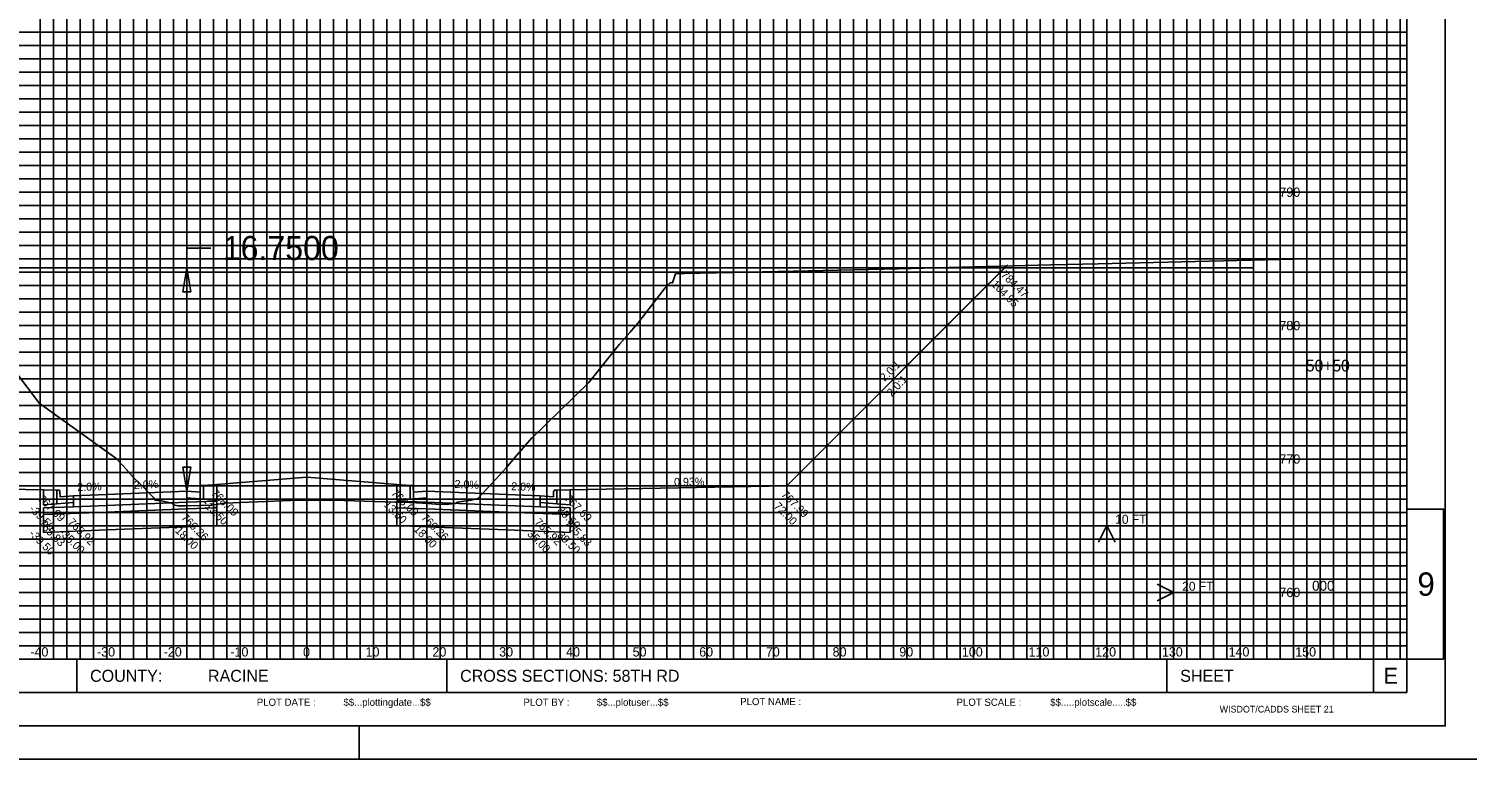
# Model space of a CAD drawing. Extents: x 578243 to 601557, y 174899 to 175559.
# Drawn here: x 600998.1 to 601213.9, y 175338.8 to 175448.3 of the extents above; entities that cross this region are included whole.
import ezdxf

# ---------------------------------------------------------------- set-up
doc = ezdxf.new("R2010")
doc.units = 0
for name, color, linetype in [('E_PROF_Grid', 7, 'Continuous'), ('E_PROF_GridMin', 7, 'Continuous'), ('P_CRDR_Label', 7, 'Continuous'), ('P_CRDR_Link', 7, 'Continuous'), ('P_E_XS_Ground', 7, 'Continuous'), ('P_RW_SlopeIntercepts', 7, 'Continuous'), ('P_XS_Text', 7, 'Continuous'), ('PLT_Sheet_Border', 7, 'Continuous'), ('PLT_Sheet_Info', 7, 'Continuous')]:
    doc.layers.add(name, color=color, linetype=linetype)

msp = doc.modelspace()

# ---------------------------------------------------------------- linework, layer by layer
at = {"layer": 'E_PROF_Grid'}
for p, q in [((600999.84, 175353.8), (600999.84, 175548.8)), ((601009.84, 175353.8), (601009.84, 175548.8)), ((601019.84, 175353.8), (601019.84, 175548.8)), ((601029.84, 175353.8), (601029.84, 175548.8)), ((601039.84, 175353.8), (601039.84, 175548.8)), ((601049.84, 175353.8), (601049.84, 175548.8)), ((601059.84, 175353.8), (601059.84, 175548.8)), ((601069.84, 175353.8), (601069.84, 175548.8)), ((601079.84, 175353.8), (601079.84, 175548.8)), ((601089.84, 175353.8), (601089.84, 175548.8)), ((601099.84, 175353.8), (601099.84, 175548.8)), ((601109.84, 175353.8), (601109.84, 175548.8)), ((601119.84, 175353.8), (601119.84, 175548.8)), ((601129.84, 175353.8), (601129.84, 175548.8)), ((601139.84, 175353.8), (601139.84, 175548.8)), ((601149.84, 175353.8), (601149.84, 175548.8)), ((601159.84, 175353.8), (601159.84, 175548.8)), ((601169.84, 175353.8), (601169.84, 175548.8)), ((601179.84, 175353.8), (601179.84, 175548.8)), ((601189.84, 175353.8), (601189.84, 175548.8)), ((601199.84, 175353.8), (601199.84, 175548.8)), ((600889.84, 175443.8), (601204.84, 175443.8)), ((600889.84, 175433.8), (601204.84, 175433.8)), ((600889.84, 175423.8), (601204.84, 175423.8)), ((600889.84, 175413.8), (601204.84, 175413.8)), ((600889.84, 175403.8), (601204.84, 175403.8)), ((600889.84, 175393.8), (601204.84, 175393.8)), ((600889.84, 175383.8), (601204.84, 175383.8)), ((600889.84, 175373.8), (601204.84, 175373.8)), ((600889.84, 175363.8), (601204.84, 175363.8))]:
    msp.add_line(p, q, dxfattribs=at)
at = {"layer": 'E_PROF_GridMin'}
for p, q in [((601001.84, 175353.8), (601001.84, 175548.8)), ((601003.84, 175353.8), (601003.84, 175548.8)), ((601005.84, 175353.8), (601005.84, 175548.8)), ((601007.84, 175353.8), (601007.84, 175548.8)), ((601011.84, 175353.8), (601011.84, 175548.8)), ((601013.84, 175353.8), (601013.84, 175548.8)), ((601015.84, 175353.8), (601015.84, 175548.8)), ((601017.84, 175353.8), (601017.84, 175548.8)), ((601021.84, 175353.8), (601021.84, 175548.8)), ((601023.84, 175353.8), (601023.84, 175548.8)), ((601025.84, 175353.8), (601025.84, 175548.8)), ((601027.84, 175353.8), (601027.84, 175548.8)), ((601031.84, 175353.8), (601031.84, 175548.8)), ((601033.84, 175353.8), (601033.84, 175548.8)), ((601035.84, 175353.8), (601035.84, 175548.8)), ((601037.84, 175353.8), (601037.84, 175548.8)), ((601041.84, 175353.8), (601041.84, 175548.8)), ((601043.84, 175353.8), (601043.84, 175548.8)), ((601045.84, 175353.8), (601045.84, 175548.8)), ((601047.84, 175353.8), (601047.84, 175548.8)), ((601051.84, 175353.8), (601051.84, 175548.8)), ((601053.84, 175353.8), (601053.84, 175548.8)), ((601055.84, 175353.8), (601055.84, 175548.8)), ((601057.84, 175353.8), (601057.84, 175548.8)), ((601061.84, 175353.8), (601061.84, 175548.8)), ((601063.84, 175353.8), (601063.84, 175548.8)), ((601065.84, 175353.8), (601065.84, 175548.8)), ((601067.84, 175353.8), (601067.84, 175548.8)), ((601071.84, 175353.8), (601071.84, 175548.8)), ((601073.84, 175353.8), (601073.84, 175548.8)), ((601075.84, 175353.8), (601075.84, 175548.8)), ((601077.84, 175353.8), (601077.84, 175548.8)), ((601081.84, 175353.8), (601081.84, 175548.8)), ((601083.84, 175353.8), (601083.84, 175548.8)), ((601085.84, 175353.8), (601085.84, 175548.8)), ((601087.84, 175353.8), (601087.84, 175548.8)), ((601091.84, 175353.8), (601091.84, 175548.8)), ((601093.84, 175353.8), (601093.84, 175548.8)), ((601095.84, 175353.8), (601095.84, 175548.8)), ((601097.84, 175353.8), (601097.84, 175548.8)), ((601101.84, 175353.8), (601101.84, 175548.8)), ((601103.84, 175353.8), (601103.84, 175548.8)), ((601105.84, 175353.8), (601105.84, 175548.8)), ((601107.84, 175353.8), (601107.84, 175548.8)), ((601111.84, 175353.8), (601111.84, 175548.8)), ((601113.84, 175353.8), (601113.84, 175548.8)), ((601115.84, 175353.8), (601115.84, 175548.8)), ((601117.84, 175353.8), (601117.84, 175548.8)), ((601121.84, 175353.8), (601121.84, 175548.8)), ((601123.84, 175353.8), (601123.84, 175548.8)), ((601125.84, 175353.8), (601125.84, 175548.8)), ((601127.84, 175353.8), (601127.84, 175548.8)), ((601131.84, 175353.8), (601131.84, 175548.8)), ((601133.84, 175353.8), (601133.84, 175548.8)), ((601135.84, 175353.8), (601135.84, 175548.8)), ((601137.84, 175353.8), (601137.84, 175548.8)), ((601141.84, 175353.8), (601141.84, 175548.8)), ((601143.84, 175353.8), (601143.84, 175548.8)), ((601145.84, 175353.8), (601145.84, 175548.8)), ((601147.84, 175353.8), (601147.84, 175548.8)), ((601151.84, 175353.8), (601151.84, 175548.8)), ((601153.84, 175353.8), (601153.84, 175548.8)), ((601155.84, 175353.8), (601155.84, 175548.8)), ((601157.84, 175353.8), (601157.84, 175548.8)), ((601161.84, 175353.8), (601161.84, 175548.8)), ((601163.84, 175353.8), (601163.84, 175548.8)), ((601165.84, 175353.8), (601165.84, 175548.8)), ((601167.84, 175353.8), (601167.84, 175548.8)), ((601171.84, 175353.8), (601171.84, 175548.8)), ((601173.84, 175353.8), (601173.84, 175548.8)), ((601175.84, 175353.8), (601175.84, 175548.8)), ((601177.84, 175353.8), (601177.84, 175548.8)), ((601181.84, 175353.8), (601181.84, 175548.8)), ((601183.84, 175353.8), (601183.84, 175548.8)), ((601185.84, 175353.8), (601185.84, 175548.8)), ((601187.84, 175353.8), (601187.84, 175548.8)), ((601191.84, 175353.8), (601191.84, 175548.8)), ((601193.84, 175353.8), (601193.84, 175548.8)), ((601195.84, 175353.8), (601195.84, 175548.8)), ((601197.84, 175353.8), (601197.84, 175548.8)), ((601201.84, 175353.8), (601201.84, 175548.8)), ((601203.84, 175353.8), (601203.84, 175548.8)), ((600889.84, 175447.8), (601204.84, 175447.8)), ((600889.84, 175445.8), (601204.84, 175445.8)), ((600889.84, 175441.8), (601204.84, 175441.8)), ((600889.84, 175439.8), (601204.84, 175439.8)), ((600889.84, 175437.8), (601204.84, 175437.8)), ((600889.84, 175435.8), (601204.84, 175435.8)), ((600889.84, 175431.8), (601204.84, 175431.8)), ((600889.84, 175429.8), (601204.84, 175429.8)), ((600889.84, 175427.8), (601204.84, 175427.8)), ((600889.84, 175425.8), (601204.84, 175425.8)), ((600889.84, 175421.8), (601204.84, 175421.8)), ((600889.84, 175419.8), (601204.84, 175419.8)), ((600889.84, 175417.8), (601204.84, 175417.8)), ((600889.84, 175415.8), (601204.84, 175415.8)), ((600889.84, 175411.8), (601204.84, 175411.8)), ((600889.84, 175409.8), (601204.84, 175409.8)), ((600889.84, 175407.8), (601204.84, 175407.8)), ((600889.84, 175405.8), (601204.84, 175405.8)), ((600889.84, 175401.8), (601204.84, 175401.8)), ((600889.84, 175399.8), (601204.84, 175399.8)), ((600889.84, 175397.8), (601204.84, 175397.8)), ((600889.84, 175395.8), (601204.84, 175395.8)), ((600889.84, 175391.8), (601204.84, 175391.8)), ((600889.84, 175389.8), (601204.84, 175389.8)), ((600889.84, 175387.8), (601204.84, 175387.8)), ((600889.84, 175385.8), (601204.84, 175385.8)), ((600889.84, 175381.8), (601204.84, 175381.8)), ((600889.84, 175379.8), (601204.84, 175379.8)), ((600889.84, 175377.8), (601204.84, 175377.8)), ((600889.84, 175375.8), (601204.84, 175375.8)), ((600889.84, 175371.8), (601204.84, 175371.8)), ((600889.84, 175369.8), (601204.84, 175369.8)), ((600889.84, 175367.8), (601204.84, 175367.8)), ((600889.84, 175365.8), (601204.84, 175365.8)), ((600889.84, 175361.8), (601204.84, 175361.8)), ((600889.84, 175359.8), (601204.84, 175359.8)), ((600889.84, 175357.8), (601204.84, 175357.8)), ((600889.84, 175355.8), (601204.84, 175355.8)), ((601207.19, 175338.8), (601217.19, 175338.8))]:
    msp.add_line(p, q, dxfattribs=at)
at = {"layer": 'P_CRDR_Link'}
msp.add_line((601144.95, 175412.9), (601111.84, 175379.78), dxfattribs=at)
for points in [[(601111.84, 175379.78), (601144.78, 175412.73)], [(601111.84, 175379.78), (601144.78, 175412.73)], [(601026.34, 175379.98), (601039.84, 175381.06)], [(601026.34, 175379.98), (601039.84, 175381.06)], [(601039.84, 175381.06), (601026.34, 175379.98)], [(601039.84, 175381.06), (601053.34, 175379.98)], [(601039.84, 175381.06), (601053.34, 175379.98)], [(601053.34, 175379.98), (601039.84, 175381.06)], [(601000.34, 175379.18), (600967.84, 175379.78)], [(601000.34, 175379.18), (600967.84, 175379.78)], [(601002.34, 175379.14), (601000.34, 175379.18)], [(601000.34, 175379.18), (601000.34, 175376.94)], [(601000.34, 175379.18), (601000.34, 175376.94)], [(601000.34, 175379.18), (601000.34, 175376.94)], [(601002.66, 175379.14), (601002.34, 175379.14)], [(601002.66, 175379.14), (601002.34, 175379.14)], [(601002.34, 175379.14), (601002.34, 175377.1)], [(601002.34, 175377.1), (601002.34, 175379.14)], [(601002.74, 175379.1), (601002.66, 175379.14)], [(601002.74, 175379.1), (601002.66, 175379.14)], [(601002.8, 175378.98), (601002.74, 175379.1)], [(601002.8, 175378.98), (601002.74, 175379.1)], [(601002.82, 175378.82), (601002.8, 175378.98)], [(601002.82, 175378.82), (601002.8, 175378.98)], [(601002.84, 175378.14), (601002.82, 175378.82)], [(601002.84, 175378.14), (601002.82, 175378.82)], [(601004.84, 175378.3), (601002.84, 175378.14)], [(601004.84, 175378.3), (601002.84, 175378.14)], [(601009.84, 175378.5), (601004.84, 175378.3)], [(601004.84, 175378.3), (601004.84, 175376.64)], [(601004.84, 175377.3), (601004.84, 175378.3)], [(601021.84, 175378.98), (601009.84, 175378.5)], [(601009.84, 175378.5), (601009.84, 175376.84)], [(601009.84, 175378.5), (601009.84, 175376.84)], [(601021.84, 175378.98), (601021.84, 175377.32)], [(601021.84, 175378.98), (601021.84, 175377.32)], [(601021.84, 175378.98), (601021.84, 175377.32)], [(601021.84, 175378.98), (601023.84, 175378.82)], [(601021.84, 175378.98), (601023.84, 175378.82)], [(601021.84, 175377.98), (601021.84, 175378.98)], [(601023.84, 175378.82), (601023.85, 175379.5)], [(601023.84, 175378.82), (601023.85, 175379.5)], [(601023.85, 175379.5), (601023.88, 175379.66)], [(601023.85, 175379.5), (601023.88, 175379.66)], [(601023.88, 175379.66), (601023.94, 175379.78)], [(601023.88, 175379.66), (601023.94, 175379.78)], [(601023.94, 175379.78), (601024.02, 175379.82)], [(601023.94, 175379.78), (601024.02, 175379.82)], [(601024.02, 175379.82), (601024.34, 175379.82)], [(601024.02, 175379.82), (601024.34, 175379.82)], [(601024.34, 175379.82), (601026.34, 175379.98)], [(601024.34, 175379.82), (601024.34, 175377.78)], [(601024.34, 175377.78), (601024.34, 175379.82)], [(601026.34, 175379.98), (601026.34, 175377.62)], [(601026.34, 175379.98), (601026.34, 175377.62)], [(601026.34, 175379.98), (601026.34, 175377.62)], [(601026.34, 175379.98), (601026.34, 175379.98)], [(601026.34, 175379.98), (601026.34, 175379.98)], [(601026.34, 175379.98), (601026.34, 175379.98)], [(601055.34, 175379.82), (601053.34, 175379.98)], [(601053.34, 175379.98), (601053.34, 175377.62)], [(601053.34, 175379.98), (601053.34, 175377.62)], [(601053.34, 175379.98), (601053.34, 175377.62)], [(601053.34, 175379.98), (601053.34, 175379.98)], [(601053.34, 175379.98), (601053.34, 175379.98)], [(601053.34, 175379.98), (601053.34, 175379.98)], [(601055.66, 175379.82), (601055.34, 175379.82)], [(601055.66, 175379.82), (601055.34, 175379.82)], [(601055.34, 175379.82), (601055.34, 175377.78)], [(601055.34, 175377.78), (601055.34, 175379.82)], [(601055.74, 175379.78), (601055.66, 175379.82)], [(601055.74, 175379.78), (601055.66, 175379.82)], [(601055.8, 175379.66), (601055.74, 175379.78)], [(601055.8, 175379.66), (601055.74, 175379.78)], [(601055.82, 175379.5), (601055.8, 175379.66)], [(601055.82, 175379.5), (601055.8, 175379.66)], [(601055.84, 175378.82), (601055.82, 175379.5)], [(601055.84, 175378.82), (601055.82, 175379.5)], [(601057.84, 175378.98), (601055.84, 175378.82)], [(601057.84, 175378.98), (601055.84, 175378.82)], [(601057.84, 175378.98), (601069.84, 175378.5)], [(601057.84, 175378.98), (601057.84, 175377.32)], [(601057.84, 175378.98), (601057.84, 175377.32)], [(601057.84, 175378.98), (601057.84, 175377.32)], [(601057.84, 175377.98), (601057.84, 175378.98)], [(601069.84, 175378.5), (601069.84, 175376.84)], [(601069.84, 175378.5), (601074.84, 175378.3)], [(601069.84, 175378.5), (601069.84, 175376.84)], [(601074.84, 175378.3), (601074.84, 175376.64)], [(601074.84, 175378.3), (601076.84, 175378.14)], [(601074.84, 175378.3), (601076.84, 175378.14)], [(601074.84, 175377.3), (601074.84, 175378.3)], [(601076.84, 175378.14), (601076.85, 175378.82)], [(601076.84, 175378.14), (601076.85, 175378.82)], [(601076.85, 175378.82), (601076.88, 175378.98)], [(601076.85, 175378.82), (601076.88, 175378.98)], [(601076.88, 175378.98), (601076.94, 175379.1)], [(601076.88, 175378.98), (601076.94, 175379.1)], [(601076.94, 175379.1), (601077.02, 175379.14)], [(601076.94, 175379.1), (601077.02, 175379.14)], [(601077.02, 175379.14), (601077.34, 175379.14)], [(601077.02, 175379.14), (601077.34, 175379.14)], [(601077.34, 175379.14), (601079.34, 175379.18)], [(601077.34, 175379.14), (601077.34, 175377.1)], [(601077.34, 175377.1), (601077.34, 175379.14)], [(601079.34, 175379.18), (601111.84, 175379.78)], [(601079.34, 175379.18), (601111.84, 175379.78)], [(601079.34, 175379.18), (601079.34, 175376.94)], [(601079.34, 175379.18), (601079.34, 175376.94)], [(601079.34, 175379.18), (601079.34, 175376.94)], [(601000.34, 175376.94), (601002.34, 175377.1)], [(601004.84, 175376.64), (601000.34, 175376.46)], [(601000.34, 175376.46), (601000.34, 175375.46)], [(601002.34, 175377.1), (601004.84, 175377.3)], [(601002.34, 175377.1), (601004.84, 175377.3)], [(601009.84, 175376.84), (601004.84, 175376.64)], [(601021.84, 175377.32), (601009.84, 175376.84)], [(601009.84, 175376.84), (601009.84, 175375.84)], [(601009.84, 175376.84), (601009.84, 175375.84)], [(601021.84, 175376.32), (601009.84, 175375.84)], [(601024.34, 175377.78), (601021.84, 175377.98)], [(601024.34, 175377.78), (601021.84, 175377.98)], [(601026.34, 175377.5), (601021.84, 175377.32)], [(601021.84, 175377.32), (601021.84, 175376.32)], [(601021.84, 175377.32), (601021.84, 175376.32)], [(601021.84, 175377.32), (601021.84, 175376.32)], [(601026.34, 175376.5), (601021.84, 175376.32)], [(601021.84, 175376.32), (601021.84, 175373.65)], [(601021.84, 175376.32), (601021.84, 175373.65)], [(601021.84, 175376.32), (601021.84, 175373.65)], [(601026.34, 175377.62), (601024.34, 175377.78)], [(601026.34, 175377.5), (601026.34, 175376.5)], [(601026.34, 175376.5), (601026.34, 175373.83)], [(601053.34, 175377.62), (601055.34, 175377.78)], [(601053.34, 175377.5), (601057.84, 175377.32)], [(601053.34, 175377.5), (601053.34, 175376.5)], [(601053.34, 175376.5), (601057.84, 175376.32)], [(601053.34, 175376.5), (601053.34, 175373.83)], [(601055.34, 175377.78), (601057.84, 175377.98)], [(601055.34, 175377.78), (601057.84, 175377.98)], [(601057.84, 175377.32), (601069.84, 175376.84)], [(601057.84, 175377.32), (601057.84, 175376.32)], [(601057.84, 175377.32), (601057.84, 175376.32)], [(601057.84, 175377.32), (601057.84, 175376.32)], [(601057.84, 175376.32), (601069.84, 175375.84)], [(601057.84, 175376.32), (601057.84, 175373.65)], [(601057.84, 175376.32), (601057.84, 175373.65)], [(601057.84, 175376.32), (601057.84, 175373.65)], [(601069.84, 175376.84), (601069.84, 175375.84)], [(601069.84, 175376.84), (601074.84, 175376.64)], [(601069.84, 175376.84), (601069.84, 175375.84)], [(601077.34, 175377.1), (601074.84, 175377.3)], [(601077.34, 175377.1), (601074.84, 175377.3)], [(601074.84, 175376.64), (601079.34, 175376.46)], [(601079.34, 175376.94), (601077.34, 175377.1)], [(601079.34, 175376.46), (601079.34, 175375.46)], [(601009.84, 175375.84), (601000.34, 175375.46)], [(601000.34, 175375.46), (601000.34, 175372.79)], [(601009.84, 175375.84), (601009.84, 175373.17)], [(601009.84, 175375.84), (601009.84, 175373.17)], [(601021.84, 175373.65), (601026.34, 175373.83)], [(601057.84, 175373.65), (601053.34, 175373.83)], [(601069.84, 175375.84), (601069.84, 175373.17)], [(601069.84, 175375.84), (601079.34, 175375.46)], [(601069.84, 175375.84), (601069.84, 175373.17)], [(601079.34, 175375.46), (601079.34, 175372.79)], [(601009.84, 175373.17), (601000.34, 175372.79)], [(601021.84, 175373.65), (601009.84, 175373.17)], [(601057.84, 175373.65), (601069.84, 175373.17)], [(601069.84, 175373.17), (601079.34, 175372.79)]]:
    msp.add_lwpolyline(points, dxfattribs=at)
at = {"layer": 'P_E_XS_Ground'}
msp.add_lwpolyline([(600994.36, 175399.25), (600999.77, 175392.14), (601000.55, 175391.58), (601002.56, 175390.11), (601005.71, 175387.86), (601008.75, 175385.68), (601008.77, 175385.66), (601011.22, 175383.92), (601012.91, 175382.11), (601012.92, 175382.09), (601013.86, 175381.05), (601014.46, 175380.43), (601014.6, 175380.31), (601014.6, 175380.31), (601016.78, 175378.08), (601017.1, 175377.64), (601017.52, 175377.58), (601018.03, 175377.53), (601019.62, 175377.17), (601020, 175376.88), (601020.57, 175376.77), (601021.58, 175376.78), (601023.84, 175376.84), (601025.58, 175376.86), (601026.5, 175377.01), (601027.49, 175377.18), (601037.42, 175377.58), (601039.84, 175377.61), (601040.92, 175377.62), (601045.43, 175377.59), (601053.1, 175377.32), (601054.18, 175377.31), (601056.28, 175377.23), (601058.06, 175377.15), (601059.74, 175376.97), (601061.17, 175377.02), (601062.08, 175377.15), (601062.44, 175377.35), (601064.51, 175377.63), (601064.91, 175377.73), (601065.5, 175377.89), (601068.86, 175381.48), (601068.87, 175381.49), (601069.73, 175382.49), (601071.11, 175384.08), (601071.12, 175384.09), (601073.59, 175386.97), (601073.62, 175387), (601082.14, 175395.28), (601086.73, 175401.04), (601088.29, 175402.76), (601089.56, 175404.24), (601089.71, 175404.43), (601093.6, 175409.47), (601094.35, 175410.22), (601094.36, 175410.25), (601094.54, 175410.23), (601094.7, 175410.23), (601095.14, 175411.56), (601096.5, 175411.6), (601098.77, 175411.66), (601103.75, 175411.74), (601128.59, 175412.32), (601151.45, 175412.9), (601158.54, 175413.04), (601189.84, 175413.79)], dxfattribs=at)
at = {"layer": 'P_RW_SlopeIntercepts'}
for p, q in [((601021.84, 175415.41), (601025.44, 175415.41)), ((601021.84, 175378.98), (601021.84, 175415.41)), ((600921.84, 175412.48), (601181.84, 175412.48))]:
    msp.add_line(p, q, dxfattribs=at)
for points in [[(601021.24, 175408.88), (601022.44, 175408.88), (601021.84, 175412.48)], [(601021.24, 175382.58), (601022.44, 175382.58), (601021.84, 175378.98)]]:
    msp.add_lwpolyline(points, close=True, dxfattribs=at)
at = {"layer": 'PLT_Sheet_Border'}
for points in [[(600877.19, 175338.8), (601217.19, 175338.8), (601217.19, 175558.8), (600877.19, 175558.8)], [(600879.59, 175343.8), (601210.59, 175343.8), (601210.59, 175553.8), (600879.59, 175553.8)]]:
    msp.add_lwpolyline(points, close=True, dxfattribs=at)
at = {"layer": 'PLT_Sheet_Info'}
for p, q in [((601204.84, 175348.8), (601204.84, 175548.8)), ((600889.84, 175353.8), (601204.84, 175353.8)), ((601005.34, 175348.8), (601005.34, 175353.8)), ((601060.84, 175348.8), (601060.84, 175353.8)), ((601168.84, 175348.8), (601168.84, 175353.8)), ((601199.84, 175348.8), (601199.84, 175353.8)), ((600889.84, 175348.8), (601204.84, 175348.8)), ((601047.69, 175338.8), (601047.69, 175343.8)), ((601042.69, 175338.8), (601052.69, 175338.8))]:
    msp.add_line(p, q, dxfattribs=at)
msp.add_lwpolyline([(601204.84, 175376.3), (601210.34, 175376.3), (601210.34, 175353.8), (601204.84, 175353.8)], close=True, dxfattribs=at)
for points in [[(601159.84, 175373.84), (601158.6, 175371.36)], [(601159.84, 175363.8), (601159.84, 175373.84), (601161.08, 175371.36)], [(601159.84, 175363.8), (601169.89, 175363.8), (601167.4, 175362.55)], [(601169.89, 175363.8), (601167.4, 175365.04)]]:
    msp.add_lwpolyline(points, dxfattribs=at)

# ---------------------------------------------------------------- texts
at = {"layer": 'P_CRDR_Label'}
for s, rotation, p in [('104.95', 315, (601142.42, 175409.91)), ('104.95', 315, (601142.42, 175409.91)), ('784.47', 315, (601143.86, 175411.32)), ('784.47', 315, (601143.86, 175411.32)), ('2.0:1', 45, (601126.5, 175395.35)), ('2.0:1', 46.711, (601127.58, 175393.07)), ('2.0%', 2.2906, (601005.43, 175378.98)), ('2.0%', 2.2906, (601013.93, 175379.32)), ('2.0%', 357.7094, (601061.98, 175379.47)), ('2.0%', 357.7094, (601070.48, 175379.13)), ('0.93%', 0.4313, (601094.93, 175379.77)), ('767.69', 315, (600999.41, 175377.77)), ('768.09', 315, (601025.41, 175378.57)), ('768.09', 315, (601052.41, 175378.57)), ('767.69', 315, (601078.41, 175377.77)), ('767.99', 315, (601110.91, 175378.37)), ('-39.50', 315, (600998.12, 175376.21)), ('-13.50', 315, (601024.12, 175377.01)), ('13.50', 315, (601051.29, 175376.85)), ('39.50', 315, (601077.31, 175376.02)), ('72.00', 315, (601109.82, 175376.62)), ('765.83', 315, (600999.41, 175374.04)), ('765.92', 315, (601003.91, 175374.22)), ('766.26', 315, (601020.91, 175374.9)), ('766.26', 315, (601020.91, 175374.9)), ('766.26', 315, (601020.91, 175374.9)), ('18.00', 315, (601055.8, 175373.17)), ('18.00', 315, (601055.8, 175373.17)), ('18.00', 315, (601055.8, 175373.17)), ('766.26', 315, (601056.91, 175374.9)), ('766.26', 315, (601056.91, 175374.9)), ('766.26', 315, (601056.91, 175374.9)), ('765.92', 315, (601073.91, 175374.22)), ('765.83', 315, (601078.41, 175374.04)), ('-39.50', 315, (600998.11, 175372.5)), ('-35.00', 315, (601002.62, 175372.67)), ('-18.00', 315, (601019.63, 175373.34)), ('-18.00', 315, (601019.63, 175373.34)), ('-18.00', 315, (601019.63, 175373.34)), ('35.00', 315, (601072.81, 175372.48)), ('39.50', 315, (601077.31, 175372.3))]:
    msp.add_text(s, height=1.2, rotation=rotation, dxfattribs=at).set_placement(p)
at = {"layer": 'P_RW_SlopeIntercepts'}
msp.add_text('16.7500', height=3.6, dxfattribs=at).set_placement((601027.24, 175413.63))
at = {"layer": 'P_XS_Text'}
for s, height, p in [('790', 1.4, (601185.72, 175423.1)), ('780', 1.4, (601185.72, 175403.1)), ('50+50', 1.75, (601189.7, 175396.93)), ('770', 1.4, (601185.72, 175383.1)), ('760', 1.4, (601185.72, 175363.1)), ('-40', 1.4, (600998.38, 175354.19)), ('-30', 1.4, (601008.38, 175354.19)), ('-20', 1.4, (601018.38, 175354.19)), ('-10', 1.4, (601028.38, 175354.19)), ('0', 1.4, (601039.28, 175354.19)), ('0', 1.4, (601039.28, 175354.19)), ('10', 1.4, (601048.66, 175354.19)), ('20', 1.4, (601058.69, 175354.19)), ('30', 1.4, (601068.7, 175354.19)), ('40', 1.4, (601078.73, 175354.19)), ('50', 1.4, (601088.71, 175354.19)), ('60', 1.4, (601098.7, 175354.19)), ('70', 1.4, (601108.7, 175354.19)), ('80', 1.4, (601118.71, 175354.19)), ('90', 1.4, (601128.71, 175354.19)), ('100', 1.4, (601138.1, 175354.19)), ('110', 1.4, (601148.1, 175354.19)), ('120', 1.4, (601158.1, 175354.19)), ('130', 1.4, (601168.1, 175354.19)), ('140', 1.4, (601178.1, 175354.19)), ('150', 1.4, (601188.1, 175354.19))]:
    msp.add_text(s, height=height, rotation=360, dxfattribs=at).set_placement(p)
at = {"layer": 'PLT_Sheet_Info'}
for s, height, p in [('  10 FT', 1.347, (601160.09, 175374.09)), ('  20 FT', 1.347, (601170.14, 175364.05)), ('     000', 1.5, (601187.84, 175364.05)), ('9', 3.5, (601206.42, 175363.3)), ('COUNTY:', 1.8, (601007.34, 175350.4)), ('       RACINE       ', 1.8, (601020.34, 175350.4)), ('CROSS SECTIONS: 58TH RD                           ', 1.8, (601062.84, 175350.4)), ('SHEET ', 1.8, (601170.84, 175350.4)), ('E', 2.4, (601201.36, 175350.11)), ('PLOT NAME :                      ', 1.08, (601104.84, 175346.9)), ('PLOT SCALE : ', 1.08, (601137.3, 175346.8)), ('$$.....plotscale.....$$', 1.08, (601151.34, 175346.8)), ('WISDOT/CADDS SHEET 21', 1, (601176.76, 175345.8))]:
    msp.add_text(s, height=height, dxfattribs=at).set_placement(p)
for s, p in [('PLOT DATE :', (601032.34, 175346.8)), ('$$...plottingdate...$$', (601045.34, 175346.8)), ('PLOT BY :', (601072.34, 175346.8)), ('$$...plotuser...$$', (601083.34, 175346.8))]:
    msp.add_text(s, height=1.08, rotation=360, dxfattribs=at).set_placement(p)

doc.saveas('drawing.dxf')
